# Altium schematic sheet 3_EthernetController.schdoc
size 309 x 223 mm; Symbol: Sheet-Symbol_A4; Device: Sheet-Symbol_A4; @Project Name: V2 - ODrive Rev Motor Module; @Page Count: 5; @Update Date: 2024-12-31; @Create Date: 2024-12-04; @Schematic Name: Schematic-A; @Page No: 3; @Page Name: EthernetController; Company: EasyEDA.com; Reviewed: EasyEDA; Version: V0.1; Page Size: A4; Part Number: JLCPCB-002; Drawn: EasyEDA; @Board Name: BaseModule; @Create Time: 20:02:26; @Update Time: 16:24:46
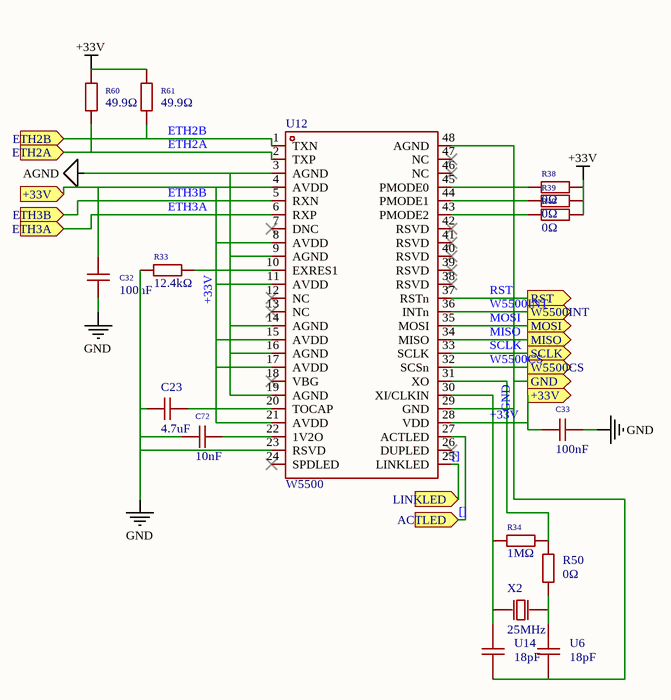
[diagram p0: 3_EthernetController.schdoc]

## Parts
C23  4.7uF  [C0603]
C32  100nF  [C0805]
C33  100nF  [C0805]
C72  10nF  [C0402]
R33  12.4kΩ  [R0402]
R34  1MΩ  [R1206]
R38  0Ω  [R0805]
R39  0Ω  [R0805]
R40  0Ω  [R0805]
R50  0Ω  [R0805]
R60  49.9Ω  [R0805]
R61  49.9Ω  [R0805]
U6  18pF  [C0201]
U12  W5500  [LQFP-48_L7.0-W7.0-P0.50-LS9.0-BL]
U14  18pF  [C0201]
X2  25MHz  [HC-49S_L11.4-W4.8]

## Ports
+33V (in), +33V (out), ACTLED (in), ETH2A (in), ETH2B (in), ETH3A (in), ETH3B (in), GND (out), LINKLED (in), MISO (out), MOSI (out), RST (out), SCLK (out), W5500CS (out), W5500INT (out)

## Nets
+33V: C32.1 C33.1 R38.2 R39.2 R40.2 R60.2 R61.2 U12.4(AVDD) U12.8(AVDD) U12.11(AVDD) U12.15(AVDD) U12.17(AVDD) U12.21(AVDD) U12.28(VDD) ; port +33V
AGND: U12.3(AGND) U12.9(AGND) U12.14(AGND) U12.16(AGND) U12.19(AGND)
GND: C23.1 C32.2 C33.2 C72.1 R33.1 U6.1 U12.23(RSVD) U12.29(GND) U12.48(AGND) U14.1 ; port GND
[]: U12.25(LINKLED) U12.27(ACTLED) ; port ACTLED, port LINKLED
ETH2A: R60.1 U12.2(TXP) ; port ETH2A
ETH2B: R61.1 U12.1(TXN) ; port ETH2B
ETH3A: U12.6(RXP) ; port ETH3A
ETH3B: U12.5(RXN) ; port ETH3B
MISO: U12.34(MISO) ; port MISO
MOSI: U12.35(MOSI) ; port MOSI
RST: U12.37(RSTn) ; port RST
SCLK: U12.33(SCLK) ; port SCLK
W5500CS: U12.32(SCSn) ; port W5500CS
W5500INT: U12.36(INTn) ; port W5500INT
NetC23_2: C23.2 U12.20(TOCAP)
NetC72_2: C72.2 U12.22(1V2O)
NetR33_2: R33.2 U12.10(EXRES1)
NetR34_1: R34.1 U12.30(XI/CLKIN) U14.2 X2.1(OSC1)
NetR34_2: R34.2 R50.2 U12.31(XO)
NetR38_1: R38.1 U12.45(PMODE0)
NetR39_1: R39.1 U12.44(PMODE1)
NetR40_1: R40.1 U12.43(PMODE2)
NetR50_1: R50.1 U6.2 X2.2(OSC2)

Not connected (* = marked no-connect by the designer): U12 7(DNC)* 12(NC)* 13(NC)* 18(VBG)* 24(SPDLED)* 26(DUPLED)* 38(RSVD)* 39(RSVD)* 40(RSVD)* 41(RSVD)* 42(RSVD)* 46(NC)* 47(NC)*

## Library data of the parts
C23 = CL10A475KQ8NNNC: Manufacturer: SAMSUNG(三星); Add into BOM: yes; Tolerance: ±10%
C32 C33 = 0805B104K500NT: Manufacturer: FH(风华); Add into BOM: yes; Tolerance: ±10%
C72 = CC0402KRX7R9BB103: Manufacturer: YAGEO(国巨); Add into BOM: yes; Tolerance: ±10%
R33 = 0402WGF1242TCE: Manufacturer: UNI-ROYAL(厚声); Add into BOM: yes; Tolerance: ±1%; Temperature Coefficient: ±100ppm/℃
R34 = 1206W4F1004T5E: Manufacturer: UNI-ROYAL(厚声); Add into BOM: yes; Tolerance: ±1%; Temperature Coefficient: ±100ppm/℃
R38-R40 = 0805W8F0000T5E_C17477: Manufacturer: UNI-ROYAL(厚声); Add into BOM: yes; Tolerance: ±1%; Temperature Coefficient: ±800ppm/℃
R50 = RC0805JR-070RL: Manufacturer: YAGEO(国巨); Add into BOM: yes; Tolerance: ±5%
R60 R61 = 0805W8F499JT5E: Manufacturer: UNI-ROYAL(厚声); Add into BOM: yes; Tolerance: ±1%; Temperature Coefficient: ±100ppm/℃
U6 U14 = GJM0335C1E180GB01D: Manufacturer: muRata(村田); Add into BOM: yes; Tolerance: ±2%; Temperature Coefficient: C0G
U12 = W5500: Manufacturer: WIZNET; Add into BOM: yes
X2 = X49SM25MSD2SC: Manufacturer: YXC(扬兴晶振); Add into BOM: yes; Crystal Type: Surface Mount Crystal; Normal temperature Frequency Tolerance: ±20ppm; Frequency Stability(Full temperature range): ±30ppm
